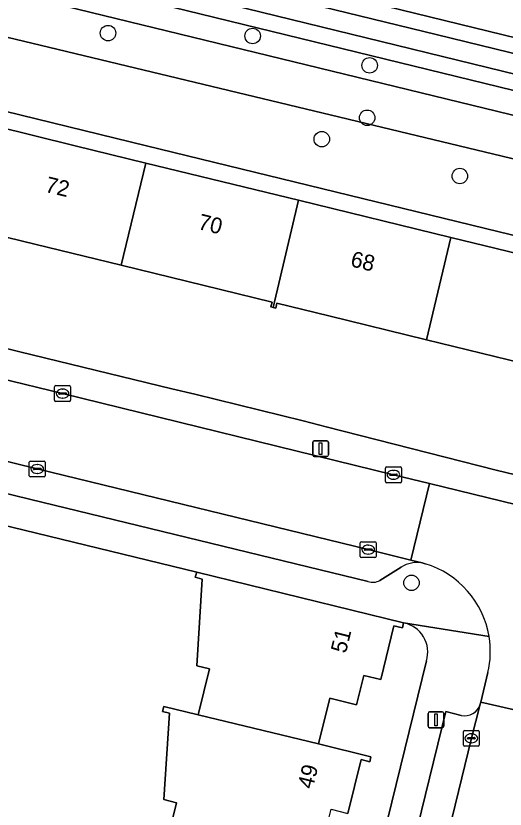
# Model space of a CAD drawing. Extents: x 163266 to 164362, y 381528 to 382286.
# Drawn here: x 163844.3 to 163875.1, y 382208.1 to 382258.2 of the extents above; entities that cross this region are included whole.
import ezdxf

# ---------------------------------------------------------------- set-up
doc = ezdxf.new("R2010")
doc.units = 0
for name, color, linetype in [('IMGEO_Berm_groen', 7, 'Continuous'), ('IMGEO_Boom', 7, 'Continuous'), ('IMGEO_Erf', 7, 'Continuous'), ('IMGEO_Groenvoorziening', 7, 'Continuous'), ('IMGEO_Kolk', 7, 'Continuous'), ('IMGEO_Lichtmast', 7, 'Continuous'), ('IMGEO_Loofbos', 7, 'Continuous'), ('IMGEO_Muur', 7, 'Continuous'), ('IMGEO_Oever', 7, 'Continuous'), ('IMGEO_Pand', 7, 'Continuous'), ('IMGEO_Pand_nummerreeks', 7, 'Continuous'), ('IMGEO_Parkeervlak_open', 7, 'Continuous'), ('IMGEO_Rijbaan_lokaal_open', 7, 'Continuous'), ('IMGEO_Voetpad_open', 7, 'Continuous'), ('IMGEO_Waterloop', 7, 'Continuous')]:
    doc.layers.add(name, color=color, linetype=linetype)

msp = doc.modelspace()

# ---------------------------------------------------------------- linework, layer by layer
at = {"layer": 'IMGEO_Berm_groen'}
msp.add_lwpolyline([(163827.813, 382268.559), (163903.688, 382250), (163972.716, 382232.791), (163990.722, 382228.949), (163990.191, 382226.629), (163993.937, 382225.807), (163994.449, 382227.946), (164000, 382226.644), (164034.633, 382218.521)], dxfattribs=at)
at = {"layer": 'IMGEO_Boom'}
for centre in [(163850.082, 382257.11), (163859.205, 382256.928), (163866.586, 382255.073), (163866.432, 382251.767), (163863.569, 382250.415), (163872.278, 382248.089), (163869.229, 382222.412)]:
    msp.add_circle(centre, 0.489, dxfattribs=at)
at = {"layer": 'IMGEO_Erf'}
for points in [[(164000, 382214.018), (163852.505, 382250), (163830.652, 382255.331), (163820.909, 382257.71), (163819.962, 382253.749), (163820.89, 382253.489), (163821.611, 382256.436), (163833.166, 382253.623), (163842.811, 382251.271), (163847.999, 382250), (163852.474, 382248.909), (163862.091, 382246.569), (163871.716, 382244.216), (163883.149, 382241.433), (163894.56, 382238.644), (163904.168, 382236.307), (163913.841, 382233.941), (163923.476, 382231.591), (163933.121, 382229.239), (163944.503, 382226.463)], [(163876.222, 382236.278), (163870.185, 382237.752), (163864.01, 382239.261), (163860.742, 382240.059), (163860.665, 382239.748), (163860.493, 382239.79), (163860.354, 382239.824), (163860.43, 382240.134), (163857.185, 382240.927), (163850.904, 382242.461), (163844.687, 382243.98), (163841.414, 382244.779), (163841.337, 382244.468), (163841.165, 382244.51), (163841.026, 382244.544), (163841.102, 382244.854), (163837.85, 382245.648), (163831.624, 382247.169), (163825.611, 382248.638), (163825.21, 382246.997), (163820.13, 382248.237)], [(163818.443, 382243.223), (163823.969, 382241.919), (163834.769, 382239.371), (163836.229, 382239.026), (163843.063, 382237.346), (163844.521, 382236.992), (163854.108, 382234.667), (163855.566, 382234.313), (163862.387, 382232.631), (163863.841, 382232.262), (163874.578, 382229.533), (163885.354, 382226.906)], [(163853.694, 382205.643), (163854.403, 382208.532), (163853.608, 382208.727), (163853.964, 382214.193), (163853.527, 382214.3), (163853.603, 382214.611), (163855.77, 382214.086), (163856.475, 382216.979), (163855.679, 382217.173), (163856.027, 382222.653), (163855.59, 382222.76), (163855.681, 382223.079), (163836.993, 382227.636)], [(163868.733, 382219.885), (163868.656, 382219.575), (163868.123, 382219.707), (163867.285, 382216.31), (163866.218, 382216.574), (163865.761, 382214.721), (163864.072, 382215.138), (163863.358, 382212.246), (163866.669, 382211.429), (163866.592, 382211.12), (163866.059, 382211.252), (163865.221, 382207.855)], [(163864.412, 382193.996), (163870.173, 382217.48)]]:
    msp.add_lwpolyline(points, dxfattribs=at)
msp.add_arc((163868.369, 382218.034), 1.887, 342.9361, 78.8862, dxfattribs=at)
at = {"layer": 'IMGEO_Groenvoorziening'}
for points in [[(163823.874, 382261.74), (163832.907, 382259.458), (163872.239, 382250), (164000, 382219.278), (164136.238, 382186.518), (164142.104, 382184.986)], [(163904.313, 382244.949), (163847.381, 382258.81)]]:
    msp.add_lwpolyline(points, dxfattribs=at)
at = {"layer": 'IMGEO_Kolk'}
for p, q in [((163846.713, 382233.932), (163846.713, 382234.784)), ((163846.788, 382234.858), (163847.64, 382234.858)), ((163847.714, 382234.784), (163847.714, 382233.932)), ((163846.972, 382234.352), (163846.972, 382234.364)), ((163847.41, 382234.315), (163847.012, 382234.315)), ((163847.015, 382234.401), (163847.413, 382234.401)), ((163847.201, 382234.638), (163847.226, 382234.638)), ((163847.456, 382234.364), (163847.456, 382234.352)), ((163847.64, 382233.858), (163846.788, 382233.858)), ((163847.224, 382234.078), (163847.199, 382234.078)), ((163845.116, 382229.173), (163845.116, 382230.025)), ((163845.191, 382230.099), (163846.043, 382230.099)), ((163845.604, 382229.879), (163845.629, 382229.879)), ((163846.117, 382230.025), (163846.117, 382229.173)), ((163845.375, 382229.593), (163845.375, 382229.605)), ((163845.813, 382229.556), (163845.415, 382229.556)), ((163845.418, 382229.642), (163845.816, 382229.642)), ((163845.627, 382229.319), (163845.602, 382229.319)), ((163845.859, 382229.605), (163845.859, 382229.593)), ((163867.591, 382228.806), (163867.591, 382229.658)), ((163867.666, 382229.732), (163868.518, 382229.732)), ((163868.079, 382229.512), (163868.104, 382229.512)), ((163868.592, 382229.658), (163868.592, 382228.806)), ((163846.043, 382229.099), (163845.191, 382229.099)), ((163867.85, 382229.226), (163867.85, 382229.238)), ((163868.288, 382229.189), (163867.89, 382229.189)), ((163867.893, 382229.275), (163868.291, 382229.275)), ((163868.102, 382228.952), (163868.077, 382228.952)), ((163868.334, 382229.238), (163868.334, 382229.226)), ((163868.518, 382228.732), (163867.666, 382228.732)), ((163865.999, 382224.084), (163865.999, 382224.936)), ((163866.074, 382225.01), (163866.926, 382225.01)), ((163866.487, 382224.79), (163866.512, 382224.79)), ((163867, 382224.936), (163867, 382224.084)), ((163866.258, 382224.504), (163866.258, 382224.516)), ((163866.696, 382224.467), (163866.298, 382224.467)), ((163866.301, 382224.553), (163866.699, 382224.553)), ((163866.742, 382224.516), (163866.742, 382224.504)), ((163866.926, 382224.01), (163866.074, 382224.01)), ((163866.51, 382224.23), (163866.485, 382224.23)), ((163872.504, 382212.176), (163872.504, 382213.028)), ((163872.579, 382213.102), (163873.431, 382213.102)), ((163872.992, 382212.882), (163873.017, 382212.882)), ((163873.505, 382213.028), (163873.505, 382212.176)), ((163872.763, 382212.596), (163872.763, 382212.608)), ((163873.201, 382212.559), (163872.803, 382212.559)), ((163872.806, 382212.645), (163873.204, 382212.645)), ((163873.015, 382212.322), (163872.99, 382212.322)), ((163873.247, 382212.608), (163873.247, 382212.596)), ((163873.431, 382212.102), (163872.579, 382212.102))]:
    msp.add_line(p, q, dxfattribs=at)
for points in [[(163846.713, 382233.932), (163846.713, 382234.784)], [(163846.788, 382234.858), (163847.64, 382234.858)], [(163847.714, 382234.784), (163847.714, 382233.932)], [(163847.64, 382233.858), (163846.788, 382233.858)], [(163845.116, 382229.173), (163845.116, 382230.025)], [(163845.191, 382230.099), (163846.043, 382230.099)], [(163846.117, 382230.025), (163846.117, 382229.173)], [(163867.591, 382228.806), (163867.591, 382229.658)], [(163867.666, 382229.732), (163868.518, 382229.732)], [(163868.592, 382229.658), (163868.592, 382228.806)], [(163846.043, 382229.099), (163845.191, 382229.099)], [(163868.518, 382228.732), (163867.666, 382228.732)], [(163865.999, 382224.084), (163865.999, 382224.936)], [(163866.074, 382225.01), (163866.926, 382225.01)], [(163867, 382224.936), (163867, 382224.084)], [(163866.926, 382224.01), (163866.074, 382224.01)], [(163872.504, 382212.176), (163872.504, 382213.028)], [(163872.579, 382213.102), (163873.431, 382213.102)], [(163873.505, 382213.028), (163873.505, 382212.176)], [(163873.431, 382212.102), (163872.579, 382212.102)]]:
    msp.add_lwpolyline(points, dxfattribs=at)
for centre, radius, start, end in [((163846.79, 382234.782), 0.0765, 91.552, 178.448), ((163846.79, 382234.782), 0.0765, 91.552, 178.448), ((163847.638, 382234.782), 0.0765, 1.552, 88.448), ((163847.638, 382234.782), 0.0765, 1.552, 88.448), ((163847.012, 382234.361), 0.0403, 85.8775, 175.7526), ((163847.009, 382234.351), 0.0366, 178.938, 274.7102), ((163847.413, 382234.358), 0.043, 264.8664, 352.4533), ((163847.417, 382234.363), 0.0386, 1.7309, 96.639), ((163846.79, 382233.934), 0.0765, 181.552, 268.448), ((163846.79, 382233.934), 0.0765, 181.552, 268.448), ((163847.638, 382233.934), 0.0765, 271.552, 358.448), ((163847.638, 382233.934), 0.0765, 271.552, 358.448), ((163845.193, 382230.023), 0.0765, 91.552, 178.448), ((163845.193, 382230.023), 0.0765, 91.552, 178.448), ((163846.041, 382230.023), 0.0765, 1.552, 88.448), ((163846.041, 382230.023), 0.0765, 1.552, 88.448), ((163845.415, 382229.602), 0.0403, 85.8775, 175.7526), ((163845.412, 382229.592), 0.0366, 178.938, 274.7102), ((163845.816, 382229.599), 0.043, 264.8664, 352.4533), ((163845.82, 382229.604), 0.0386, 1.7309, 96.639), ((163867.668, 382229.656), 0.0765, 91.552, 178.448), ((163867.668, 382229.656), 0.0765, 91.552, 178.448), ((163868.516, 382229.656), 0.0765, 1.552, 88.448), ((163868.516, 382229.656), 0.0765, 1.552, 88.448), ((163845.193, 382229.175), 0.0765, 181.552, 268.448), ((163845.193, 382229.175), 0.0765, 181.552, 268.448), ((163846.041, 382229.175), 0.0765, 271.552, 358.448), ((163846.041, 382229.175), 0.0765, 271.552, 358.448), ((163867.668, 382228.808), 0.0765, 181.552, 268.448), ((163867.668, 382228.808), 0.0765, 181.552, 268.448), ((163867.89, 382229.235), 0.0403, 85.8775, 175.7526), ((163867.887, 382229.225), 0.0366, 178.938, 274.7102), ((163868.291, 382229.232), 0.043, 264.8664, 352.4533), ((163868.295, 382229.237), 0.0386, 1.7309, 96.639), ((163868.516, 382228.808), 0.0765, 271.552, 358.448), ((163868.516, 382228.808), 0.0765, 271.552, 358.448), ((163866.076, 382224.934), 0.0765, 91.552, 178.448), ((163866.076, 382224.934), 0.0765, 91.552, 178.448), ((163866.924, 382224.934), 0.0765, 1.552, 88.448), ((163866.924, 382224.934), 0.0765, 1.552, 88.448), ((163866.298, 382224.513), 0.0403, 85.8775, 175.7526), ((163866.295, 382224.503), 0.0366, 178.938, 274.7102), ((163866.699, 382224.51), 0.043, 264.8664, 352.4533), ((163866.703, 382224.515), 0.0386, 1.7309, 96.639), ((163866.076, 382224.086), 0.0765, 181.552, 268.448), ((163866.076, 382224.086), 0.0765, 181.552, 268.448), ((163866.924, 382224.086), 0.0765, 271.552, 358.448), ((163866.924, 382224.086), 0.0765, 271.552, 358.448), ((163872.581, 382213.026), 0.0765, 91.552, 178.448), ((163872.581, 382213.026), 0.0765, 91.552, 178.448), ((163873.429, 382213.026), 0.0765, 1.552, 88.448), ((163873.429, 382213.026), 0.0765, 1.552, 88.448), ((163872.803, 382212.605), 0.0403, 85.8775, 175.7526), ((163872.8, 382212.595), 0.0366, 178.938, 274.7102), ((163873.204, 382212.602), 0.043, 264.8664, 352.4533), ((163873.208, 382212.607), 0.0386, 1.7309, 96.639), ((163872.581, 382212.178), 0.0765, 181.552, 268.448), ((163872.581, 382212.178), 0.0765, 181.552, 268.448), ((163873.429, 382212.178), 0.0765, 271.552, 358.448), ((163873.429, 382212.178), 0.0765, 271.552, 358.448)]:
    msp.add_arc(centre, radius, start, end, dxfattribs=at)
for centre, major_axis, ratio, start_param, end_param in [((163847.2, 382234.358), (-0.387, 0.002), 0.722429, 4.712389, 7.853982), ((163847.225, 382234.358), (-0.39, 0.002), 0.717154, 1.570796, 4.712389), ((163845.603, 382229.599), (-0.387, 0.002), 0.722429, 4.712389, 7.853982), ((163845.628, 382229.599), (-0.39, 0.002), 0.717154, 1.570796, 4.712389), ((163868.078, 382229.232), (-0.387, 0.002), 0.722429, 4.712389, 7.853982), ((163868.103, 382229.232), (-0.39, 0.002), 0.717154, 1.570796, 4.712389), ((163866.486, 382224.51), (-0.387, 0.002), 0.722429, 4.712389, 7.853982), ((163866.511, 382224.51), (-0.39, 0.002), 0.717154, 1.570796, 4.712389), ((163872.991, 382212.602), (-0.387, 0.002), 0.722429, 4.712389, 7.853982), ((163873.016, 382212.602), (-0.39, 0.002), 0.717154, 1.570796, 4.712389)]:
    msp.add_ellipse(centre, major_axis=major_axis, ratio=ratio, start_param=start_param, end_param=end_param, dxfattribs=at)
at = {"layer": 'IMGEO_Lichtmast'}
for p, q in [((163862.994, 382230.484), (163862.994, 382231.284)), ((163862.994, 382231.284), (163862.994, 382230.484)), ((163863.094, 382231.384), (163863.884, 382231.384)), ((163863.884, 382231.384), (163863.094, 382231.384)), ((163863.984, 382231.284), (163863.984, 382230.484)), ((163863.984, 382230.484), (163863.984, 382231.284)), ((163863.884, 382230.384), (163863.094, 382230.384)), ((163863.094, 382230.384), (163863.884, 382230.384)), ((163870.374, 382214.269), (163871.164, 382214.269)), ((163871.164, 382214.269), (163870.374, 382214.269)), ((163870.274, 382213.369), (163870.274, 382214.169)), ((163870.274, 382214.169), (163870.274, 382213.369)), ((163871.264, 382214.169), (163871.264, 382213.369)), ((163871.264, 382213.369), (163871.264, 382214.169)), ((163871.164, 382213.269), (163870.374, 382213.269)), ((163870.374, 382213.269), (163871.164, 382213.269))]:
    msp.add_line(p, q, dxfattribs=at)
for points in [[(163863.414, 382231.259), (163863.564, 382231.259), (163863.564, 382230.509), (163863.414, 382230.509), (163863.414, 382231.259)], [(163870.694, 382214.144), (163870.844, 382214.144), (163870.844, 382213.394), (163870.694, 382213.394), (163870.694, 382214.144)]]:
    msp.add_lwpolyline(points, dxfattribs=at)
for centre, start, end in [((163863.094, 382231.284), 90, 180), ((163863.094, 382231.284), 90, 180), ((163863.884, 382231.284), 0, 90), ((163863.884, 382231.284), 360, 90), ((163863.094, 382230.484), 180, 270), ((163863.094, 382230.484), 180, 270), ((163863.884, 382230.484), 270, 0), ((163863.884, 382230.484), 270, 0), ((163870.374, 382214.169), 90, 180), ((163870.374, 382214.169), 90, 180), ((163871.164, 382214.169), 0, 90), ((163871.164, 382214.169), 360, 90), ((163870.374, 382213.369), 180, 270), ((163870.374, 382213.369), 180, 270), ((163871.164, 382213.369), 270, 0), ((163871.164, 382213.369), 270, 0)]:
    msp.add_arc(centre, 0.1, start, end, dxfattribs=at)
at = {"layer": 'IMGEO_Loofbos'}
for points in [[(164142.104, 382184.986), (164136.238, 382186.518), (164000, 382219.278), (163872.239, 382250), (163832.907, 382259.458), (163823.874, 382261.74)], [(163817.409, 382251.574), (163819.3, 382251.045), (163819.962, 382253.749), (163820.909, 382257.71), (163830.652, 382255.331), (163852.505, 382250), (164000, 382214.018), (164033.312, 382205.891), (164134.264, 382181.264), (164140.582, 382179.712)]]:
    msp.add_lwpolyline(points, dxfattribs=at)
msp.add_lwpolyline([(163902.877, 382246.848), (163889.989, 382250), (163847.869, 382260.302), (163847.381, 382258.81), (163904.313, 382244.949), (163904.766, 382246.403)], close=True, dxfattribs=at)
at = {"layer": 'IMGEO_Muur'}
for points in [[(163844.521, 382236.992), (163854.108, 382234.667)], [(163863.841, 382232.262), (163874.578, 382229.533)], [(163855.681, 382223.079), (163836.993, 382227.636)]]:
    msp.add_lwpolyline(points, dxfattribs=at)
at = {"layer": 'IMGEO_Oever'}
for points in [[(163903.688, 382250), (163827.813, 382268.559)], [(163958.066, 382234.869), (163932.961, 382240.785), (163881.588, 382253.084), (163857.852, 382258.89), (163848.107, 382261.273), (163837.34, 382263.906), (163827.273, 382266.368), (163827.064, 382266.492), (163826.972, 382266.676), (163826.952, 382266.745), (163827.04, 382267.031), (163827.102, 382267.143), (163827.191, 382267.259), (163827.269, 382267.331), (163827.557, 382267.492), (163827.786, 382267.536), (163843.496, 382263.694), (163870.789, 382257.018), (163894.966, 382251.104), (163922.095, 382244.38), (163946.192, 382238.373)], [(163826.892, 382265.432), (163847.869, 382260.302), (163889.989, 382250), (163902.877, 382246.848), (163904.766, 382246.403), (163972.208, 382230.508), (163990.191, 382226.629), (163990.722, 382228.949), (163972.716, 382232.791), (163903.688, 382250)]]:
    msp.add_lwpolyline(points, dxfattribs=at)
at = {"layer": 'IMGEO_Pand'}
for points in [[(163841.165, 382244.51), (163841.337, 382244.468), (163841.414, 382244.779), (163844.687, 382243.98), (163850.904, 382242.461), (163852.474, 382248.909), (163847.999, 382250), (163842.811, 382251.271), (163842.502, 382250)], [(163850.904, 382242.461), (163857.185, 382240.927), (163860.43, 382240.134), (163860.354, 382239.824), (163860.493, 382239.79), (163862.091, 382246.569), (163852.474, 382248.909)], [(163870.185, 382237.752), (163871.716, 382244.216), (163862.091, 382246.569), (163860.493, 382239.79), (163860.665, 382239.748), (163860.742, 382240.059), (163864.01, 382239.261)], [(163881.107, 382232.949), (163883.149, 382241.433), (163871.716, 382244.216), (163870.185, 382237.752), (163876.222, 382236.278), (163875.822, 382234.637), (163880.894, 382233.39), (163880.824, 382233.025)], [(163863.358, 382212.246), (163864.072, 382215.138), (163865.761, 382214.721), (163866.218, 382216.574), (163867.285, 382216.31), (163868.123, 382219.707), (163868.656, 382219.575), (163868.733, 382219.885), (163855.681, 382223.079), (163855.59, 382222.76), (163856.027, 382222.653), (163855.679, 382217.173), (163856.475, 382216.979), (163855.77, 382214.086)], [(163863.358, 382212.246), (163855.77, 382214.086), (163853.603, 382214.611), (163853.527, 382214.3), (163853.964, 382214.193), (163853.608, 382208.727), (163854.403, 382208.532), (163853.694, 382205.643), (163861.291, 382203.812), (163862.002, 382206.694), (163863.7, 382206.275), (163864.154, 382208.119), (163865.221, 382207.855), (163866.059, 382211.252), (163866.592, 382211.12), (163866.669, 382211.429)]]:
    msp.add_lwpolyline(points, close=True, dxfattribs=at)
at = {"layer": 'IMGEO_Parkeervlak_open'}
for points in [[(163869.912, 382223.666), (163869.181, 382223.841), (163866.501, 382224.512), (163845.616, 382229.599), (163826.72, 382234.254), (163823.271, 382235.111)], [(163825.622, 382232.458), (163845.133, 382227.702), (163866.485, 382222.49)], [(163867.238, 382222.557), (163868.583, 382223.399)], [(163872.36, 382214.046), (163871.405, 382214.284), (163867.035, 382196.505), (163868.973, 382196.036), (163869.494, 382198.205), (163873.007, 382212.602), (163873.566, 382214.755)]]:
    msp.add_lwpolyline(points, dxfattribs=at)
for centre, radius, start, end in [((163869.583, 382221.864), 1.832, 79.6403, 123.0791), ((163866.776, 382223.479), 1.031, 253.5754, 296.5939), ((163872.589, 382215.037), 1.017, 256.9907, 343.9113)]:
    msp.add_arc(centre, radius, start, end, dxfattribs=at)
at = {"layer": 'IMGEO_Rijbaan_lokaal_open'}
for points in [[(163847.214, 382234.356), (163827.306, 382239.21), (163822.223, 382240.426), (163817.995, 382241.479), (163817.019, 382241.718), (163812.105, 382242.923), (163812.076, 382242.806), (163811.502, 382240.518), (163810.878, 382238.026)], [(163823.007, 382235.177), (163823.271, 382235.111), (163826.72, 382234.254), (163845.616, 382229.599), (163866.501, 382224.512), (163869.181, 382223.841), (163870.358, 382228.687), (163868.091, 382229.231), (163847.214, 382234.356)], [(163887.667, 382224.454), (163870.358, 382228.687), (163869.181, 382223.841), (163869.912, 382223.666), (163870.1, 382223.621)], [(163874.051, 382216.753), (163873.597, 382214.888), (163878.49, 382213.763), (163878.917, 382215.504)]]:
    msp.add_lwpolyline(points, dxfattribs=at)
msp.add_lwpolyline([(163869.958, 382178.945), (163870.145, 382179.708), (163873.864, 382194.892), (163874.335, 382196.824), (163878.406, 382213.423), (163878.49, 382213.763), (163873.597, 382214.888), (163873.566, 382214.755), (163873.007, 382212.602), (163869.494, 382198.205), (163868.973, 382196.036), (163865.288, 382180.883), (163865.094, 382180.087), (163864.773, 382178.809), (163869.659, 382177.662)], close=True, dxfattribs=at)
for centre, radius, start, end in [((163868.406, 382218.077), 5.797, 9.391, 73.0056), ((163868.392, 382218.074), 5.811, 346.8638, 9.402)]:
    msp.add_arc(centre, radius, start, end, dxfattribs=at)
at = {"layer": 'IMGEO_Voetpad_open'}
for points in [[(163885.354, 382226.906), (163874.578, 382229.533), (163863.841, 382232.262), (163862.387, 382232.631), (163855.566, 382234.313), (163854.108, 382234.667), (163844.521, 382236.992), (163843.063, 382237.346), (163836.229, 382239.026), (163834.769, 382239.371), (163823.969, 382241.919), (163818.443, 382243.223), (163817.995, 382241.479), (163822.223, 382240.426), (163827.306, 382239.21), (163847.214, 382234.356), (163868.091, 382229.231), (163870.358, 382228.687), (163887.667, 382224.454)], [(163845.133, 382227.702), (163825.622, 382232.458)], [(163823.948, 382230.818), (163836.993, 382227.636), (163855.681, 382223.079), (163868.733, 382219.885), (163874.125, 382219.023)], [(163866.485, 382222.49), (163845.133, 382227.702)], [(163868.583, 382223.399), (163867.238, 382222.557)], [(163870.1, 382223.621), (163869.912, 382223.666)], [(163874.125, 382219.023), (163868.733, 382219.885)], [(163870.173, 382217.48), (163864.412, 382193.996), (163866.368, 382193.511), (163864.927, 382187.613), (163863.395, 382181.341), (163862.354, 382177.116)], [(163873.566, 382214.755), (163873.597, 382214.888), (163874.051, 382216.753)], [(163864.288, 382176.968), (163864.773, 382178.809), (163865.094, 382180.087), (163865.288, 382180.883), (163868.973, 382196.036), (163867.035, 382196.505), (163871.405, 382214.284), (163872.36, 382214.046)]]:
    msp.add_lwpolyline(points, dxfattribs=at)
for centre, radius, start, end in [((163869.583, 382221.864), 1.832, 79.6403, 123.0791), ((163868.406, 382218.077), 5.797, 9.391, 73.0056), ((163866.776, 382223.479), 1.031, 253.5754, 296.5939), ((163868.369, 382218.034), 1.887, 342.9361, 78.8862), ((163868.392, 382218.074), 5.811, 346.8638, 9.402), ((163872.589, 382215.037), 1.017, 256.9907, 343.9113)]:
    msp.add_arc(centre, radius, start, end, dxfattribs=at)
at = {"layer": 'IMGEO_Waterloop'}
msp.add_lwpolyline([(163946.192, 382238.373), (163922.095, 382244.38), (163894.966, 382251.104), (163870.789, 382257.018), (163843.496, 382263.694), (163827.786, 382267.536), (163827.557, 382267.492), (163827.269, 382267.331), (163827.191, 382267.259), (163827.102, 382267.143), (163827.04, 382267.031), (163826.952, 382266.745), (163826.972, 382266.676), (163827.064, 382266.492), (163827.273, 382266.368), (163837.34, 382263.906), (163848.107, 382261.273), (163857.852, 382258.89), (163881.588, 382253.084), (163932.961, 382240.785), (163958.066, 382234.869)], dxfattribs=at)

# ---------------------------------------------------------------- texts
at = {"layer": 'IMGEO_Pand_nummerreeks'}
for s, rotation, p in [('72', 346.2934, (163846.06, 382247.103)), ('70', 346.2951, (163855.706, 382244.75)), ('68', 346.2919, (163865.327, 382242.404)), ('51', 76.1425, (163865.087, 382217.92)), ('49', 76.1425, (163862.995, 382209.355))]:
    msp.add_text(s, height=1, rotation=rotation, dxfattribs=at).set_placement(p)

doc.saveas('drawing.dxf')
